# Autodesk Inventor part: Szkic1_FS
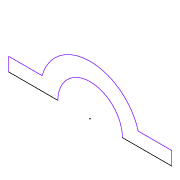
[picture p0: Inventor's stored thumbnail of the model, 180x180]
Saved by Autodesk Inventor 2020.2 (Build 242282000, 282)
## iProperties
Created: 2013-11
Part Number: Szkic1_FS
Material: Ogólny
Document SubType Name: Modeling
Designer: F.Stasiak
Density: 1 g/cm^3
Appearance: Domyślna
Manager: www.cadconsulting.pl
Company: Fabian Stasiak CAD Consulting
Author: F.Stasiak
Subject: Zbiór ćwiczeń. Autodesk Inventor 2020. Kurs podstawowy
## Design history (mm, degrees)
sketch "Szkic1"
  geometry: L1 (-15.33, 4.312)-(-26.002, 4.312); L2 (-26.002, 4.312)-(-26.002, 0); L3 (-26.002, 0)-(-10.293, 0); L4 (10.293, 0)-(26.002, 0); L5 (26.002, 0)-(26.002, 4.312); L6 (26.002, 4.312)-(15.33, 4.312); A1 r 10.293 centre (0, 0) between (10.293, 0) and (-10.293, 0); A2 r 15.925 centre (0, 0) between (15.33, 4.312) and (-15.33, 4.312); 1 further point
  constraints: 12 end point, 4 point on circle, 3 collinear, 3 perpendicular, 2 centre point, 1 coincident, 1 concentric, 1 horizontal, 1 point on line, 1 other
